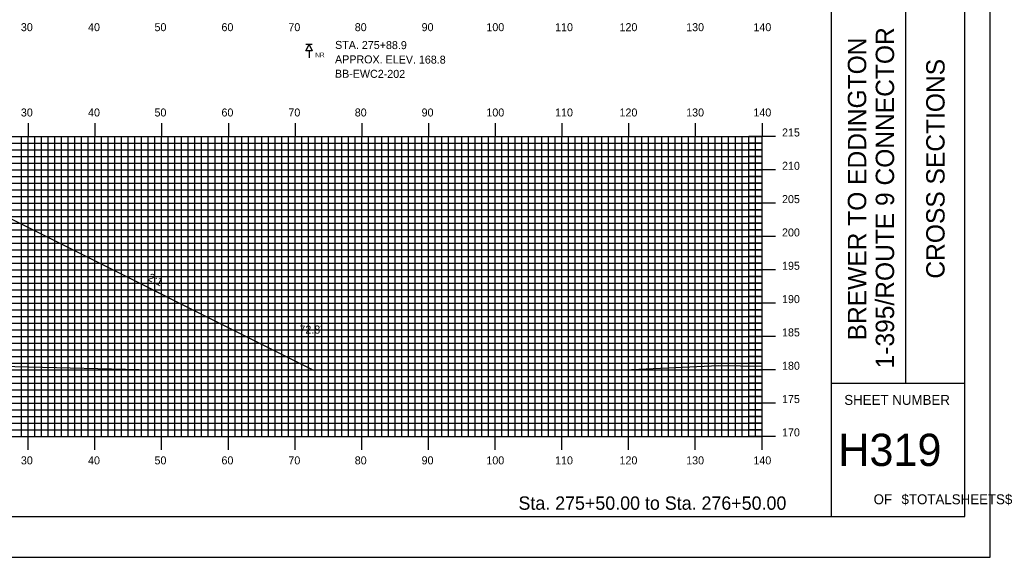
# Model space of a CAD drawing. Extents: x 1809800 to 1810143, y 442591 to 442811.
# Drawn here: x 1809994.1 to 1810142.8, y 442590.5 to 442671.2 of the extents above; entities that cross this region are included whole.
import ezdxf

# ---------------------------------------------------------------- set-up
doc = ezdxf.new("R2010")
doc.units = 0
for name, color, linetype in [('ANNOTATION', 7, 'Continuous'), ('BORDER', 7, 'Continuous'), ('BORING - NO REFUSAL', 7, 'Continuous'), ('D_Roadway_Centerline', 7, 'Continuous'), ('D_Roadway_SlopeLines', 7, 'Continuous'), ('D_Text_Standard', 7, 'Continuous'), ('H_V ANNOTATION', 7, 'Continuous'), ('MAJOR', 7, 'Continuous'), ('MINOR', 7, 'Continuous'), ('PLOT BOUNDARY', 7, 'Continuous'), ('S_Roadway_Centerline', 7, 'Continuous')]:
    doc.layers.add(name, color=color, linetype=linetype)

msp = doc.modelspace()

# ---------------------------------------------------------------- linework, layer by layer
at = {"layer": 'BORDER'}
for p, q in [((1810115.75, 442596.67), (1810115.75, 442806.67)), ((1810126.93, 442616.67), (1810126.93, 442686.67)), ((1810115.75, 442616.67), (1810135.75, 442616.67))]:
    msp.add_line(p, q, dxfattribs=at)
msp.add_lwpolyline([(1809815.75, 442596.67), (1810135.75, 442596.67), (1810135.75, 442806.67), (1809815.75, 442806.67)], close=True, dxfattribs=at)
at = {"layer": 'BORING - NO REFUSAL'}
for p, q in [((1810037.93, 442667.47), (1810036.97, 442667.47)), ((1810037.45, 442666.51), (1810037.45, 442665.45))]:
    msp.add_line(p, q, dxfattribs=at)
msp.add_lwpolyline([(1810037.45, 442667.47), (1810037.93, 442666.51), (1810036.97, 442666.51)], close=True, dxfattribs=at)
at = {"layer": 'D_Roadway_Centerline'}
msp.add_lwpolyline([(1809889.88, 442618.74), (1809937.14, 442642.37), (1809942.35, 442644.98), (1809945.35, 442645.04), (1809953.35, 442645.2), (1809965.35, 442644.62), (1809977.35, 442644.04), (1809985.35, 442643.66), (1809988.35, 442643.52), (1809993.88, 442640.75), (1810038.12, 442618.63)], dxfattribs=at)
at = {"layer": 'D_Roadway_SlopeLines'}
msp.add_lwpolyline([(1809988.35, 442643.52), (1810038.12, 442618.63)], dxfattribs=at)
at = {"layer": 'MAJOR'}
for p, q in [((1809995.35, 442655.67), (1809995.35, 442653.67)), ((1810005.35, 442655.67), (1810005.35, 442653.67)), ((1810015.35, 442655.67), (1810015.35, 442653.67)), ((1810025.35, 442655.67), (1810025.35, 442653.67)), ((1810035.35, 442655.67), (1810035.35, 442653.67)), ((1810045.35, 442655.67), (1810045.35, 442653.67)), ((1810055.35, 442655.67), (1810055.35, 442653.67)), ((1810065.35, 442655.67), (1810065.35, 442653.67)), ((1810075.35, 442655.67), (1810075.35, 442653.67)), ((1810085.35, 442655.67), (1810085.35, 442653.67)), ((1810095.35, 442655.67), (1810095.35, 442653.67)), ((1810105.35, 442655.67), (1810105.35, 442653.67)), ((1809825.35, 442653.67), (1810105.35, 442653.67)), ((1809825.35, 442653.67), (1810105.35, 442653.67)), ((1809995.35, 442608.67), (1809995.35, 442653.67)), ((1810005.35, 442608.67), (1810005.35, 442653.67)), ((1810015.35, 442608.67), (1810015.35, 442653.67)), ((1810025.35, 442608.67), (1810025.35, 442653.67)), ((1810035.35, 442608.67), (1810035.35, 442653.67)), ((1810045.35, 442608.67), (1810045.35, 442653.67)), ((1810055.35, 442608.67), (1810055.35, 442653.67)), ((1810065.35, 442608.67), (1810065.35, 442653.67)), ((1810075.35, 442608.67), (1810075.35, 442653.67)), ((1810085.35, 442608.67), (1810085.35, 442653.67)), ((1810095.35, 442608.67), (1810095.35, 442653.67)), ((1810107.35, 442653.67), (1810103.35, 442653.67)), ((1810105.35, 442608.67), (1810105.35, 442653.67)), ((1810105.35, 442608.67), (1810105.35, 442653.67)), ((1809825.35, 442648.67), (1810105.35, 442648.67)), ((1810107.35, 442648.67), (1810103.35, 442648.67)), ((1809825.35, 442643.67), (1810105.35, 442643.67)), ((1810107.35, 442643.67), (1810103.35, 442643.67)), ((1809825.35, 442638.67), (1810105.35, 442638.67)), ((1810107.35, 442638.67), (1810103.35, 442638.67)), ((1809825.35, 442633.67), (1810105.35, 442633.67)), ((1810107.35, 442633.67), (1810103.35, 442633.67)), ((1809825.35, 442628.67), (1810105.35, 442628.67)), ((1810107.35, 442628.67), (1810103.35, 442628.67)), ((1809825.35, 442623.67), (1810105.35, 442623.67)), ((1810107.35, 442623.67), (1810103.35, 442623.67)), ((1809825.35, 442618.67), (1810105.35, 442618.67)), ((1810107.35, 442618.67), (1810103.35, 442618.67)), ((1809825.35, 442613.67), (1810105.35, 442613.67)), ((1810107.35, 442613.67), (1810103.35, 442613.67)), ((1809825.35, 442608.67), (1810105.35, 442608.67)), ((1809825.35, 442608.67), (1810105.35, 442608.67)), ((1809995.35, 442606.66), (1809995.35, 442608.67)), ((1810005.35, 442606.66), (1810005.35, 442608.67)), ((1810015.35, 442606.66), (1810015.35, 442608.67)), ((1810025.35, 442606.66), (1810025.35, 442608.67)), ((1810035.35, 442606.66), (1810035.35, 442608.67)), ((1810045.35, 442606.66), (1810045.35, 442608.67)), ((1810055.35, 442606.66), (1810055.35, 442608.67)), ((1810065.35, 442606.66), (1810065.35, 442608.67)), ((1810075.35, 442606.66), (1810075.35, 442608.67)), ((1810085.35, 442606.66), (1810085.35, 442608.67)), ((1810095.35, 442606.66), (1810095.35, 442608.67)), ((1810107.35, 442608.67), (1810103.35, 442608.67)), ((1810105.35, 442606.66), (1810105.35, 442608.67))]:
    msp.add_line(p, q, dxfattribs=at)
at = {"layer": 'MINOR'}
for p, q in [((1809994.35, 442608.67), (1809994.35, 442653.67)), ((1809996.35, 442608.67), (1809996.35, 442653.67)), ((1809997.35, 442608.67), (1809997.35, 442653.67)), ((1809998.35, 442608.67), (1809998.35, 442653.67)), ((1809999.35, 442608.67), (1809999.35, 442653.67)), ((1810000.35, 442608.67), (1810000.35, 442653.67)), ((1810001.35, 442608.67), (1810001.35, 442653.67)), ((1810002.35, 442608.67), (1810002.35, 442653.67)), ((1810003.35, 442608.67), (1810003.35, 442653.67)), ((1810004.35, 442608.67), (1810004.35, 442653.67)), ((1810006.35, 442608.67), (1810006.35, 442653.67)), ((1810007.35, 442608.67), (1810007.35, 442653.67)), ((1810008.35, 442608.67), (1810008.35, 442653.67)), ((1810009.35, 442608.67), (1810009.35, 442653.67)), ((1810010.35, 442608.67), (1810010.35, 442653.67)), ((1810011.35, 442608.67), (1810011.35, 442653.67)), ((1810012.35, 442608.67), (1810012.35, 442653.67)), ((1810013.35, 442608.67), (1810013.35, 442653.67)), ((1810014.35, 442608.67), (1810014.35, 442653.67)), ((1810016.35, 442608.67), (1810016.35, 442653.67)), ((1810017.35, 442608.67), (1810017.35, 442653.67)), ((1810018.35, 442608.67), (1810018.35, 442653.67)), ((1810019.35, 442608.67), (1810019.35, 442653.67)), ((1810020.35, 442608.67), (1810020.35, 442653.67)), ((1810021.35, 442608.67), (1810021.35, 442653.67)), ((1810022.35, 442608.67), (1810022.35, 442653.67)), ((1810023.35, 442608.67), (1810023.35, 442653.67)), ((1810024.35, 442608.67), (1810024.35, 442653.67)), ((1810026.35, 442608.67), (1810026.35, 442653.67)), ((1810027.35, 442608.67), (1810027.35, 442653.67)), ((1810028.35, 442608.67), (1810028.35, 442653.67)), ((1810029.35, 442608.67), (1810029.35, 442653.67)), ((1810030.35, 442608.67), (1810030.35, 442653.67)), ((1810031.35, 442608.67), (1810031.35, 442653.67)), ((1810032.35, 442608.67), (1810032.35, 442653.67)), ((1810033.35, 442608.67), (1810033.35, 442653.67)), ((1810034.35, 442608.67), (1810034.35, 442653.67)), ((1810036.35, 442608.67), (1810036.35, 442653.67)), ((1810037.35, 442608.67), (1810037.35, 442653.67)), ((1810038.35, 442608.67), (1810038.35, 442653.67)), ((1810039.35, 442608.67), (1810039.35, 442653.67)), ((1810040.35, 442608.67), (1810040.35, 442653.67)), ((1810041.35, 442608.67), (1810041.35, 442653.67)), ((1810042.35, 442608.67), (1810042.35, 442653.67)), ((1810043.35, 442608.67), (1810043.35, 442653.67)), ((1810044.35, 442608.67), (1810044.35, 442653.67)), ((1810046.35, 442608.67), (1810046.35, 442653.67)), ((1810047.35, 442608.67), (1810047.35, 442653.67)), ((1810048.35, 442608.67), (1810048.35, 442653.67)), ((1810049.35, 442608.67), (1810049.35, 442653.67)), ((1810050.35, 442608.67), (1810050.35, 442653.67)), ((1810051.35, 442608.67), (1810051.35, 442653.67)), ((1810052.35, 442608.67), (1810052.35, 442653.67)), ((1810053.35, 442608.67), (1810053.35, 442653.67)), ((1810054.35, 442608.67), (1810054.35, 442653.67)), ((1810056.35, 442608.67), (1810056.35, 442653.67)), ((1810057.35, 442608.67), (1810057.35, 442653.67)), ((1810058.35, 442608.67), (1810058.35, 442653.67)), ((1810059.35, 442608.67), (1810059.35, 442653.67)), ((1810060.35, 442608.67), (1810060.35, 442653.67)), ((1810061.35, 442608.67), (1810061.35, 442653.67)), ((1810062.35, 442608.67), (1810062.35, 442653.67)), ((1810063.35, 442608.67), (1810063.35, 442653.67)), ((1810064.35, 442608.67), (1810064.35, 442653.67)), ((1810066.35, 442608.67), (1810066.35, 442653.67)), ((1810067.35, 442608.67), (1810067.35, 442653.67)), ((1810068.35, 442608.67), (1810068.35, 442653.67)), ((1810069.35, 442608.67), (1810069.35, 442653.67)), ((1810070.35, 442608.67), (1810070.35, 442653.67)), ((1810071.35, 442608.67), (1810071.35, 442653.67)), ((1810072.35, 442608.67), (1810072.35, 442653.67)), ((1810073.35, 442608.67), (1810073.35, 442653.67)), ((1810074.35, 442608.67), (1810074.35, 442653.67)), ((1810076.35, 442608.67), (1810076.35, 442653.67)), ((1810077.35, 442608.67), (1810077.35, 442653.67)), ((1810078.35, 442608.67), (1810078.35, 442653.67)), ((1810079.35, 442608.67), (1810079.35, 442653.67)), ((1810080.35, 442608.67), (1810080.35, 442653.67)), ((1810081.35, 442608.67), (1810081.35, 442653.67)), ((1810082.35, 442608.67), (1810082.35, 442653.67)), ((1810083.35, 442608.67), (1810083.35, 442653.67)), ((1810084.35, 442608.67), (1810084.35, 442653.67)), ((1810086.35, 442608.67), (1810086.35, 442653.67)), ((1810087.35, 442608.67), (1810087.35, 442653.67)), ((1810088.35, 442608.67), (1810088.35, 442653.67)), ((1810089.35, 442608.67), (1810089.35, 442653.67)), ((1810090.35, 442608.67), (1810090.35, 442653.67)), ((1810091.35, 442608.67), (1810091.35, 442653.67)), ((1810092.35, 442608.67), (1810092.35, 442653.67)), ((1810093.35, 442608.67), (1810093.35, 442653.67)), ((1810094.35, 442608.67), (1810094.35, 442653.67)), ((1810096.35, 442608.67), (1810096.35, 442653.67)), ((1810097.35, 442608.67), (1810097.35, 442653.67)), ((1810098.35, 442608.67), (1810098.35, 442653.67)), ((1810099.35, 442608.67), (1810099.35, 442653.67)), ((1810100.35, 442608.67), (1810100.35, 442653.67)), ((1810101.35, 442608.67), (1810101.35, 442653.67)), ((1810102.35, 442608.67), (1810102.35, 442653.67)), ((1810103.35, 442608.67), (1810103.35, 442653.67)), ((1810104.35, 442608.67), (1810104.35, 442653.67)), ((1809825.35, 442652.67), (1810105.35, 442652.67)), ((1809825.35, 442651.67), (1810105.35, 442651.67)), ((1810105.35, 442652.67), (1810103.35, 442652.67)), ((1810105.35, 442651.67), (1810103.35, 442651.67)), ((1809825.35, 442650.67), (1810105.35, 442650.67)), ((1810105.35, 442650.67), (1810103.35, 442650.67)), ((1809825.35, 442649.67), (1810105.35, 442649.67)), ((1810105.35, 442649.67), (1810103.35, 442649.67)), ((1809825.35, 442647.67), (1810105.35, 442647.67)), ((1810105.35, 442647.67), (1810103.35, 442647.67)), ((1809825.35, 442646.67), (1810105.35, 442646.67)), ((1809825.35, 442645.67), (1810105.35, 442645.67)), ((1810105.35, 442646.67), (1810103.35, 442646.67)), ((1810105.35, 442645.67), (1810103.35, 442645.67)), ((1809825.35, 442644.67), (1810105.35, 442644.67)), ((1810105.35, 442644.67), (1810103.35, 442644.67)), ((1809825.35, 442642.67), (1810105.35, 442642.67)), ((1810105.35, 442642.67), (1810103.35, 442642.67)), ((1809825.35, 442641.67), (1810105.35, 442641.67)), ((1810105.35, 442641.67), (1810103.35, 442641.67)), ((1809825.35, 442640.67), (1810105.35, 442640.67)), ((1809825.35, 442639.67), (1810105.35, 442639.67)), ((1810105.35, 442640.67), (1810103.35, 442640.67)), ((1810105.35, 442639.67), (1810103.35, 442639.67)), ((1809825.35, 442637.67), (1810105.35, 442637.67)), ((1809825.35, 442636.67), (1810105.35, 442636.67)), ((1810105.35, 442637.67), (1810103.35, 442637.67)), ((1810105.35, 442636.67), (1810103.35, 442636.67)), ((1809825.35, 442635.67), (1810105.35, 442635.67)), ((1810105.35, 442635.67), (1810103.35, 442635.67)), ((1809825.35, 442634.67), (1810105.35, 442634.67)), ((1810105.35, 442634.67), (1810103.35, 442634.67)), ((1809825.35, 442632.67), (1810105.35, 442632.67)), ((1810105.35, 442632.67), (1810103.35, 442632.67)), ((1809825.35, 442631.67), (1810105.35, 442631.67)), ((1809825.35, 442630.67), (1810105.35, 442630.67)), ((1810105.35, 442631.67), (1810103.35, 442631.67)), ((1810105.35, 442630.67), (1810103.35, 442630.67)), ((1809825.35, 442629.67), (1810105.35, 442629.67)), ((1810105.35, 442629.67), (1810103.35, 442629.67)), ((1809825.35, 442627.67), (1810105.35, 442627.67)), ((1810105.35, 442627.67), (1810103.35, 442627.67)), ((1809825.35, 442626.67), (1810105.35, 442626.67)), ((1810105.35, 442626.67), (1810103.35, 442626.67)), ((1809825.35, 442625.67), (1810105.35, 442625.67)), ((1809825.35, 442624.67), (1810105.35, 442624.67)), ((1810105.35, 442625.67), (1810103.35, 442625.67)), ((1810105.35, 442624.67), (1810103.35, 442624.67)), ((1809825.35, 442622.67), (1810105.35, 442622.67)), ((1809825.35, 442621.67), (1810105.35, 442621.67)), ((1810105.35, 442622.67), (1810103.35, 442622.67)), ((1810105.35, 442621.67), (1810103.35, 442621.67)), ((1809825.35, 442620.67), (1810105.35, 442620.67)), ((1810105.35, 442620.67), (1810103.35, 442620.67)), ((1809825.35, 442619.67), (1810105.35, 442619.67)), ((1810105.35, 442619.67), (1810103.35, 442619.67)), ((1809825.35, 442617.67), (1810105.35, 442617.67)), ((1810105.35, 442617.67), (1810103.35, 442617.67)), ((1809825.35, 442616.67), (1810105.35, 442616.67)), ((1809825.35, 442615.67), (1810105.35, 442615.67)), ((1810105.35, 442616.67), (1810103.35, 442616.67)), ((1810105.35, 442615.67), (1810103.35, 442615.67)), ((1809825.35, 442614.67), (1810105.35, 442614.67)), ((1810105.35, 442614.67), (1810103.35, 442614.67)), ((1809825.35, 442612.67), (1810105.35, 442612.67)), ((1810105.35, 442612.67), (1810103.35, 442612.67)), ((1809825.35, 442611.67), (1810105.35, 442611.67)), ((1810105.35, 442611.67), (1810103.35, 442611.67)), ((1809825.35, 442610.67), (1810105.35, 442610.67)), ((1809825.35, 442609.67), (1810105.35, 442609.67)), ((1810105.35, 442610.67), (1810103.35, 442610.67)), ((1810105.35, 442609.67), (1810103.35, 442609.67))]:
    msp.add_line(p, q, dxfattribs=at)
at = {"layer": 'PLOT BOUNDARY'}
msp.add_lwpolyline([(1809799.56, 442590.55), (1810139.56, 442590.55), (1810139.56, 442810.55), (1809799.56, 442810.55)], close=True, dxfattribs=at)
at = {"layer": 'S_Roadway_Centerline'}
msp.add_lwpolyline([(1809825.35, 442617.68), (1809830.33, 442617.73), (1809838.49, 442617.91), (1809868.24, 442618.39), (1809884.81, 442618.77), (1809887.68, 442618.75), (1809897.53, 442618.7), (1809921.01, 442618.91), (1809956.01, 442619.3), (1809959.39, 442619.17), (1809963.41, 442619.2), (1809991.29, 442619.23), (1810016.11, 442618.63), (1810025.9, 442618.65), (1810059.8, 442618.6), (1810084.68, 442618.68), (1810098.88, 442619.31), (1810105.35, 442619.22)], dxfattribs=at)

# ---------------------------------------------------------------- texts
at = {"layer": 'ANNOTATION'}
msp.add_text('2:1', height=1.2, rotation=333.4349, dxfattribs=at).set_placement((1810013.17, 442632.14))
at = {"layer": 'BORDER'}
for s, p in [('1-395/ROUTE 9 CONNECTOR', (1810125.15, 442618.87)), ('BREWER TO EDDINGTON', (1810120.97, 442623.07)), ('CROSS SECTIONS', (1810132.72, 442632.34))]:
    msp.add_text(s, height=2.7557, rotation=90, dxfattribs=at).set_placement(p)
for s, height, p in [('SHEET NUMBER', 1.4905, (1810117.68, 442613.4)), ('H319', 4.839, (1810116.78, 442604.23)), ('OF', 1.491, (1810122.08, 442598.49)), ('$TOTALSHEETS$', 1.4905, (1810126.26, 442598.49))]:
    msp.add_text(s, height=height, dxfattribs=at).set_placement(p)
at = {"layer": 'BORING - NO REFUSAL'}
for s, p in [('STA. 275+88.9', (1810041.35, 442666.81)), ('APPROX. ELEV. 168.8', (1810041.34, 442664.65)), ('BB-EWC2-202', (1810041.33, 442662.49))]:
    msp.add_text(s, height=1.2, rotation=359.8142, dxfattribs=at).set_placement(p)
msp.add_text('NR', height=0.7, dxfattribs=at).set_placement((1810038.38, 442665.55))
at = {"layer": 'D_Text_Standard'}
msp.add_text("72.8'", height=1.2, dxfattribs=at).set_placement((1810036, 442624.1))
at = {"layer": 'H_V ANNOTATION'}
for s, height, p in [('30', 1.2, (1809994.25, 442669.47)), ('40', 1.2, (1810004.32, 442669.47)), ('50', 1.2, (1810014.28, 442669.47)), ('60', 1.2, (1810024.32, 442669.47)), ('70', 1.2, (1810034.35, 442669.47)), ('80', 1.2, (1810044.3, 442669.47)), ('90', 1.2, (1810054.32, 442669.47)), ('100', 1.2, (1810064.03, 442669.47)), ('110', 1.2, (1810074.33, 442669.47)), ('120', 1.2, (1810083.99, 442669.47)), ('130', 1.2, (1810093.98, 442669.47)), ('140', 1.2, (1810104.06, 442669.47)), ('30', 1.2, (1809994.25, 442656.67)), ('40', 1.2, (1810004.32, 442656.67)), ('50', 1.2, (1810014.28, 442656.67)), ('60', 1.2, (1810024.32, 442656.67)), ('70', 1.2, (1810034.35, 442656.67)), ('80', 1.2, (1810044.3, 442656.67)), ('90', 1.2, (1810054.32, 442656.67)), ('100', 1.2, (1810064.03, 442656.67)), ('110', 1.2, (1810074.33, 442656.67)), ('120', 1.2, (1810083.99, 442656.67)), ('130', 1.2, (1810093.98, 442656.67)), ('140', 1.2, (1810104.06, 442656.67)), ('215', 1.2, (1810108.35, 442653.67)), ('210', 1.2, (1810108.35, 442648.67)), ('205', 1.2, (1810108.35, 442643.67)), ('200', 1.2, (1810108.35, 442638.67)), ('195', 1.2, (1810108.35, 442633.67)), ('190', 1.2, (1810108.35, 442628.67)), ('185', 1.2, (1810108.35, 442623.67)), ('180', 1.2, (1810108.35, 442618.67)), ('175', 1.2, (1810108.35, 442613.67)), ('170', 1.2, (1810108.35, 442608.67)), ('30', 1.2, (1809994.25, 442604.47)), ('40', 1.2, (1810004.32, 442604.47)), ('50', 1.2, (1810014.28, 442604.47)), ('60', 1.2, (1810024.32, 442604.47)), ('70', 1.2, (1810034.35, 442604.47)), ('80', 1.2, (1810044.3, 442604.47)), ('90', 1.2, (1810054.32, 442604.47)), ('100', 1.2, (1810064.03, 442604.47)), ('110', 1.2, (1810074.33, 442604.47)), ('120', 1.2, (1810083.99, 442604.47)), ('130', 1.2, (1810093.98, 442604.47)), ('140', 1.2, (1810104.06, 442604.47)), ('Sta. 275+50.00 to Sta. 276+50.00', 2.0004, (1810068.84, 442597.66))]:
    msp.add_text(s, height=height, dxfattribs=at).set_placement(p)

doc.saveas('drawing.dxf')
